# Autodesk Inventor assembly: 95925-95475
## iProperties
Author: Administrator
Shininess: 64.0
Angle Display Precision: 2
Document Length Units: 11272
Document Angle Units: 11286
Document Time Units: 11279
Document Mass Units: 11290
Document Length Units Precision: 3
Document Angle Units Precision: 2
Compacted: True
PropertySet Name: _Private Model Information
Created: 2002-04
Part Number: 95925-95475
Document SubType Name: Assembly
Designer: Administrator
Control State: 0
Master: False
Checked Out: False
PropertySet Name: Design Tracking Control
Density: 0.0
Volumn: 0.0
Area: 0.0
PropertySet Name: Model Information
